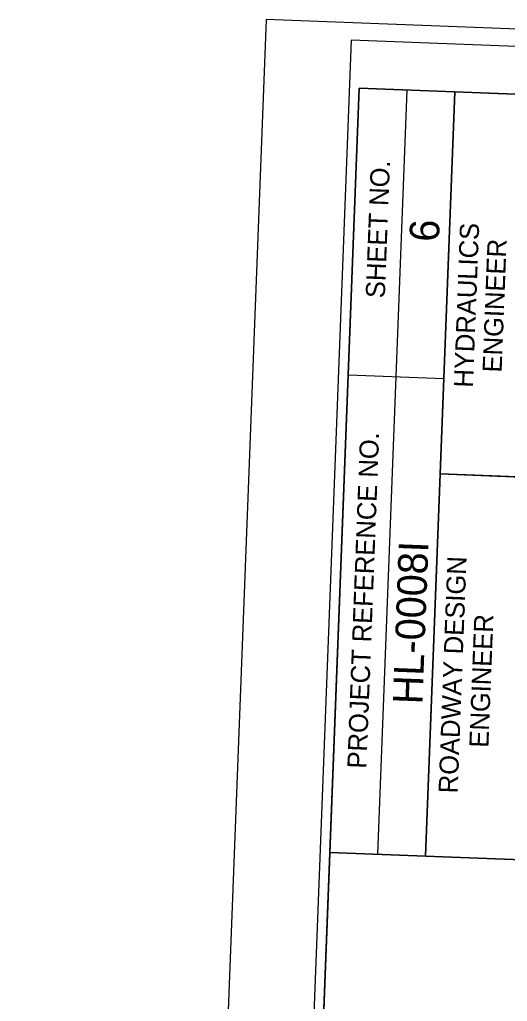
# Model space of a CAD drawing. Extents: x 2097096 to 2098260, y 686401 to 688363.
# Drawn here: x 2097096 to 2097223.6, y 687937.5 to 688194.3 of the extents above; entities that cross this region are included whole.
import ezdxf

# ---------------------------------------------------------------- set-up
doc = ezdxf.new("R2010")
doc.units = 0
for name, color, linetype in [('Sheet Data Field CELL', 7, 'Continuous'), ('Sheet Layout Plan Border', 7, 'Continuous'), ('Sheet Plot Border Inside CELL', 7, 'Continuous'), ('Sheet Plot Border Outside CELL', 7, 'Continuous'), ('Sheet Profile CELL', 7, 'Continuous')]:
    doc.layers.add(name, color=color, linetype=linetype)

msp = doc.modelspace()

# ---------------------------------------------------------------- linework, layer by layer
at = {"layer": 'Sheet Layout Plan Border'}
msp.add_lwpolyline([(2098179.19, 686705.44), (2097129.59, 686735.95), (2097177.17, 687976.48), (2097364.33, 687969.3), (2097368.7, 688083.22), (2098230.76, 688050.16)], close=True, dxfattribs=at)
at = {"layer": 'Sheet Plot Border Inside CELL'}
msp.add_lwpolyline([(2098173.22, 686483.26), (2098237.09, 688148.54), (2097182.76, 688188.97), (2097118.9, 686523.7)], close=True, dxfattribs=at)
at = {"layer": 'Sheet Plot Border Outside CELL'}
msp.add_lwpolyline([(2098195.16, 686469.41), (2098259.69, 688152.17), (2097160.5, 688194.33), (2097095.97, 686511.57)], close=True, dxfattribs=at)
at = {"layer": 'Sheet Profile CELL'}
for p, q in [((2097189.71, 687976), (2097197.37, 688175.9)), ((2097182.01, 688101.44), (2097206.99, 688100.48)), ((2097206.03, 688075.5), (2097318.4, 688071.19))]:
    msp.add_line(p, q, dxfattribs=at)
for points in [[(2097184.83, 688176.38), (2097127.35, 686677.48), (2098176.58, 686637.25), (2098234.06, 688136.14)], [(2097177.17, 687976.48), (2097184.83, 688176.38), (2097209.86, 688175.42), (2097202.2, 687975.52)], [(2097206.03, 688075.5), (2097209.86, 688175.42), (2097322.28, 688171.11), (2097318.45, 688071.19)], [(2097202.2, 687975.52), (2097206.03, 688075.5), (2097318.45, 688071.19), (2097314.61, 687971.21)]]:
    msp.add_lwpolyline(points, close=True, dxfattribs=at)

# ---------------------------------------------------------------- texts
at = {"layer": 'Sheet Data Field CELL'}
for s, p in [('6', (2097205.69, 688136.12)), ('HL-0008I', (2097201.35, 688015.14))]:
    msp.add_text(s, height=7.75, rotation=87.8037, dxfattribs=at).set_placement(p)
at = {"layer": 'Sheet Profile CELL'}
for s, height, p in [('SHEET NO.', 5, (2097191.52, 688121.4)), ('HYDRAULICS', 5, (2097214.59, 688098)), ('ENGINEER', 5, (2097222.09, 688101.96)), ('PROJECT REFERENCE NO.', 5.0001, (2097186.7, 687998.34)), ('ROADWAY DESIGN', 5.0001, (2097210.57, 687991.87)), ('ENGINEER', 5, (2097218.63, 688003.82))]:
    msp.add_text(s, height=height, rotation=87.8037, dxfattribs=at).set_placement(p)

doc.saveas('drawing.dxf')
